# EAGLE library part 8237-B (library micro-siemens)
MICROPROCESSOR/PERIPHERAL DEVICE
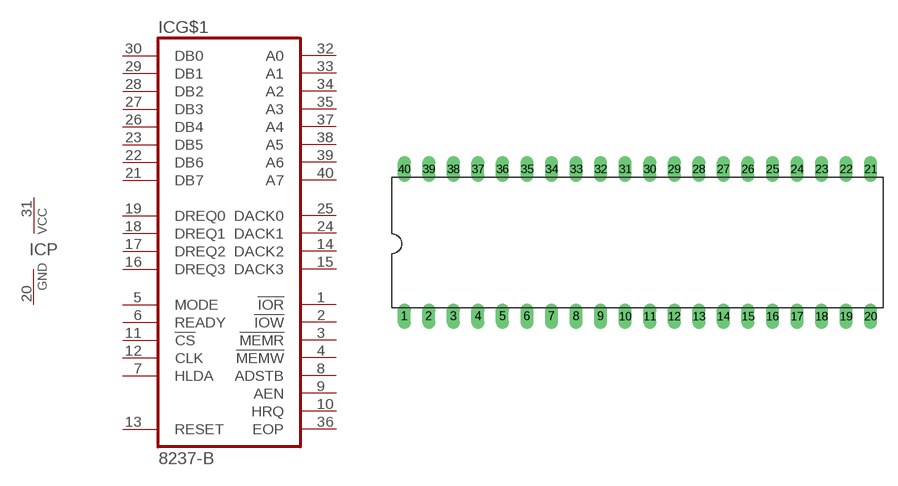
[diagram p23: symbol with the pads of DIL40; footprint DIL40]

Designator prefix IC; gates G$1=8237-B P=VCCGND

## 8237-B (OC_FARNELL: unknown; OC_NEWARK: unknown)  [DIL40]
1  G$1:!IOR
2  G$1:!IOW
3  G$1:!MEMR  out
4  G$1:!MEMW  out
5  G$1:MODE  in
6  G$1:READY  in
7  G$1:HLDA  in
8  G$1:ADSTB  out
9  G$1:AEN  out
10  G$1:HRQ  out
11  G$1:!CS  in
12  G$1:CLK  in
13  G$1:RESET  in
14  G$1:DACK2  out
15  G$1:DACK3  out
16  G$1:DREQ3  in
17  G$1:DREQ2  in
18  G$1:DREQ1  in
19  G$1:DREQ0  in
20  P:GND  pwr
21  G$1:DB7
22  G$1:DB6
23  G$1:DB5
24  G$1:DACK1  out
25  G$1:DACK0  out
26  G$1:DB4
27  G$1:DB3
28  G$1:DB2
29  G$1:DB1
30  G$1:DB0
31  P:VCC  pwr
32  G$1:A0
33  G$1:A1
34  G$1:A2
35  G$1:A3
36  G$1:EOP
37  G$1:A4  out
38  G$1:A5  out
39  G$1:A6  out
40  G$1:A7  out

## Footprint DIL40 (pad centres in mm)
Dual In Line Package
drill 0.813 long: 1 -24.13,-7.62; 2 -21.59,-7.62; 3 -19.05,-7.62; 4 -16.51,-7.62; 5 -13.97,-7.62; 6 -11.43,-7.62; 7 -8.89,-7.62; 8 -6.35,-7.62; 9 -3.81,-7.62; 10 -1.27,-7.62; 11 1.27,-7.62; 12 3.81,-7.62; 13 6.35,-7.62; 14 8.89,-7.62; 15 11.43,-7.62; 16 13.97,-7.62; 17 16.51,-7.62; 18 19.05,-7.62; 19 21.59,-7.62; 20 24.13,-7.62; 21 24.13,7.62; 22 21.59,7.62; 23 19.05,7.62; 24 16.51,7.62; 25 13.97,7.62; 26 11.43,7.62; 27 8.89,7.62; 28 6.35,7.62; 29 3.81,7.62; 30 1.27,7.62; 31 -1.27,7.62; 32 -3.81,7.62; 33 -6.35,7.62; 34 -8.89,7.62; 35 -11.43,7.62; 36 -13.97,7.62; 37 -16.51,7.62; 38 -19.05,7.62; 39 -21.59,7.62; 40 -24.13,7.62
